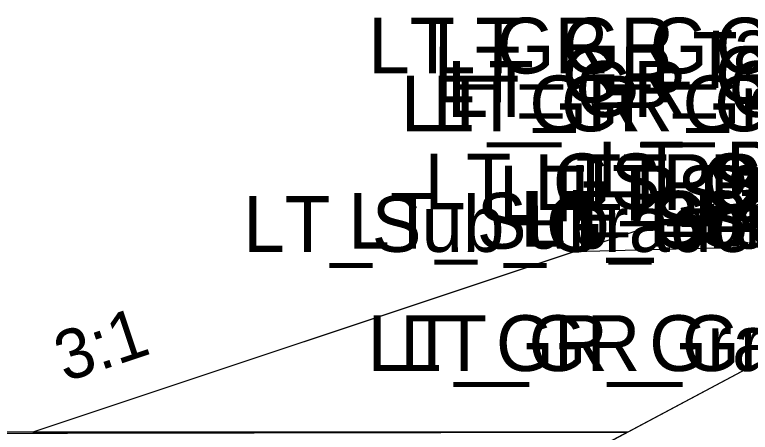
# Model space of a CAD drawing. Extents: x -14026 to 1303, y -10 to 9533.
# Drawn here: x 115.37 to 130.21, y 6004.43 to 6012.85 of the extents above; entities that cross this region are included whole.
import ezdxf

# ---------------------------------------------------------------- set-up
doc = ezdxf.new("R2010")
doc.units = 0
for name, color, linetype in [('Exist XS Ground Line', 7, 'Continuous'), ('Old_Level_10', 7, 'Continuous'), ('Prop CMT Slope Grass', 7, 'Continuous'), ('Prop CMT Subgrade Earthwork', 7, 'Continuous'), ('Prop XS Earthwork Shape', 7, 'Continuous'), ('Prop XS Side Slope Text', 7, 'Continuous'), ('Scratch_Level_0', 7, 'Continuous'), ('Scratch_Level_3', 7, 'Continuous')]:
    doc.layers.add(name, color=color, linetype=linetype)

msp = doc.modelspace()

# ---------------------------------------------------------------- linework, layer by layer
at = {"layer": 'Exist XS Ground Line'}
msp.add_lwpolyline([(112.649, 6001.933), (119.248, 6002.291), (123.411, 6002.115), (125.916, 6003.46), (130.864, 6006.093), (132.172, 6006.475), (134.127, 6007.027), (138.687, 6008.015), (139.357, 6008.208), (140.497, 6008.263), (143.06, 6008.353), (144.268, 6008.711), (145.224, 6009.02), (150, 6008.932), (156.143, 6008.819), (159.995, 6008.918)], dxfattribs=at)
at = {"layer": 'Old_Level_10'}
msp.add_lwpolyline([(119.248, 6002.291), (117.01, 6002.178), (112.649, 6001.933), (107.565, 6001.007), (112.655, 6004.4), (127.732, 6004.426), (125.916, 6003.46), (123.411, 6002.115)], close=True, dxfattribs=at)
at = {"layer": 'Prop CMT Slope Grass'}
msp.add_line((115.733, 6004.426), (127.732, 6004.426), dxfattribs=at)
for points in [[(132.235, 6009.162), (129.234, 6008.922)], [(129.234, 6008.922), (115.733, 6004.426)]]:
    msp.add_lwpolyline(points, dxfattribs=at)
at = {"layer": 'Prop CMT Subgrade Earthwork'}
msp.add_line((115.733, 6004.426), (127.732, 6004.426), dxfattribs=at)
for points in [[(126.659, 6008.064), (115.733, 6004.426)], [(129.234, 6008.129), (126.659, 6008.064)], [(130.752, 6008.167), (129.234, 6008.129)]]:
    msp.add_lwpolyline(points, dxfattribs=at)
at = {"layer": 'Prop XS Earthwork Shape'}
for points in [[(138, 6009.306), (132.235, 6009.162), (129.234, 6008.922), (115.733, 6004.426), (127.732, 6004.426), (130.864, 6006.093), (132.172, 6006.475), (134.127, 6007.027), (138.687, 6008.015), (139.357, 6008.208), (140.497, 6008.263), (143.06, 6008.353), (144.268, 6008.711), (145.224, 6009.02), (150, 6008.932), (156.143, 6008.819), (159.995, 6008.918), (167.024, 6009.181), (162, 6009.306), (150, 6009.606), (143.06, 6009.433)], [(130.752, 6008.167), (129.234, 6008.129), (126.659, 6008.064), (115.733, 6004.426), (127.732, 6004.426), (130.864, 6006.093), (132.172, 6006.475), (134.127, 6007.027), (138.687, 6008.015), (139.357, 6008.208), (140.497, 6008.263), (143.06, 6008.353), (143.508, 6008.486), (138, 6008.348)]]:
    msp.add_lwpolyline(points, close=True, dxfattribs=at)
at = {"layer": 'Scratch_Level_3'}
msp.add_line((127.732, 6004.426), (102.458, 6004.426), dxfattribs=at)

# ---------------------------------------------------------------- texts
at = {"layer": 'Prop XS Side Slope Text'}
msp.add_text('3:1', height=1, rotation=18.4178, dxfattribs=at).set_placement((116.383, 6005.433))
at = {"layer": 'Scratch_Level_0'}
for s, p in [('LT_GR_Graphics Out 03', (122.5, 6011.661)), ('LT_GR_Graphics Out 02', (123.826, 6011.661)), ('LT_GR_Out', (128.203, 6011.37)), ('LT_GR_Graphics Out 09', (123.817, 6011.078)), ('LT_GR_Graphics Out 08', (124.087, 6010.786)), ('LT_GR_Graphics Out 06', (123.16, 6010.495)), ('LT_GR_Graphics Out 07', (123.798, 6010.495)), ('LT_PS1_OEOP', (127.127, 6009.162)), ('LT_GS_OS_CTL', (123.634, 6008.922)), ('LT_PS2_Shelf Out', (125.851, 6008.906)), ('LT_PS2_OEOP', (126.794, 6008.906)), ('LT_PS3_Shelf Out', (125.137, 6008.68)), ('LT_PS3_OEOP', (126.58, 6008.692)), ('LT_Sub_Graded_Tie', (119.98, 6008.064)), ('LT_Sub_Graded_CTL', (122.1, 6008.129)), ('LT_PS4_OEOP', (125.567, 6008.167)), ('LT_Sub_OEOP', (125.655, 6008.167)), ('LT_GR_Graphics Out 04', (122.486, 6005.661)), ('LT_GR_Graphics Out 05', (123.143, 6005.661))]:
    msp.add_text(s, height=1.125, dxfattribs=at).set_placement(p)

doc.saveas('drawing.dxf')
